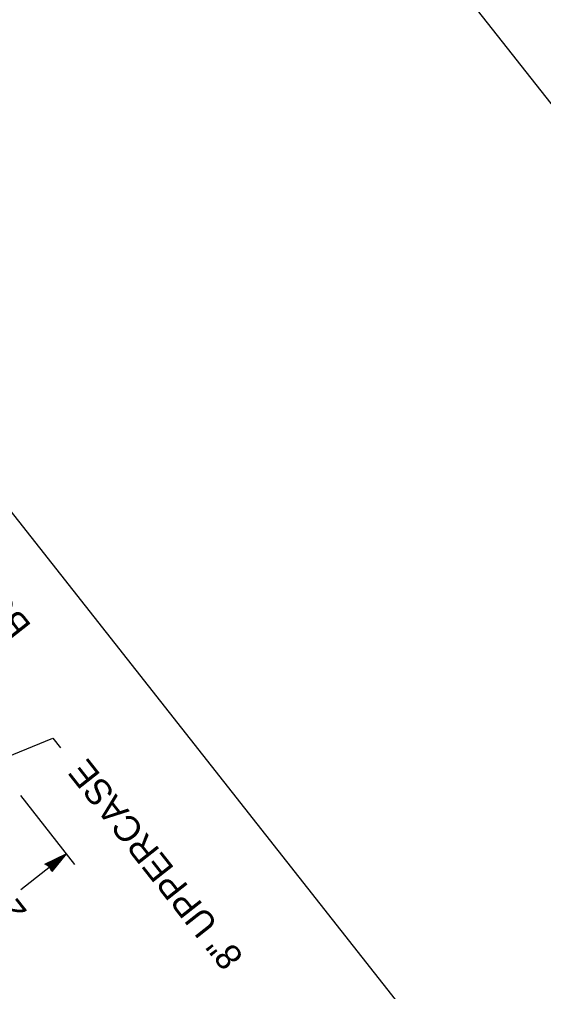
# Model space of a CAD drawing. Extents: x 671946 to 673995, y 1673066 to 1674936.
# Drawn here: x 672764.3 to 672849.6, y 1673606 to 1673764.1 of the extents above; entities that cross this region are included whole.
import ezdxf

# ---------------------------------------------------------------- set-up
doc = ezdxf.new("R2010")
doc.units = 0
doc.layers.add('1', color=7, linetype='Continuous')
doc.layers.add('Level 1', color=7, linetype='Continuous')

msp = doc.modelspace()

# ---------------------------------------------------------------- linework, layer by layer
at = {"layer": '1'}
msp.add_line((672460.47, 1674245.5), (673047.73, 1673500.58), dxfattribs=at)
at = {"layer": 'Level 1'}
for p, q in [((672685.68, 1673782.02), (672825.47, 1673604.71)), ((672764.49, 1673637.89), (672773.31, 1673626.69)), ((672764.56, 1673622.6), (672771.95, 1673628.43)), ((672768.48, 1673626.72), (672771.95, 1673628.43)), ((672768.68, 1673626.77), (672771.53, 1673628.07)), ((672768.84, 1673626.74), (672771.69, 1673628.16)), ((672768.96, 1673626.66), (672771.16, 1673627.81)), ((672768.96, 1673626.66), (672771.09, 1673627.69)), ((672769.14, 1673626.61), (672770.65, 1673627.35)), ((672769.31, 1673626.57), (672770.27, 1673627.08)), ((672771.16, 1673627.81), (672769.6, 1673626.1)), ((672771.95, 1673628.43), (672769.63, 1673625.52)), ((672771.73, 1673628.19), (672769.64, 1673625.67)), ((672771.09, 1673627.69), (672769.64, 1673625.97)), ((672771.38, 1673627.91), (672769.65, 1673625.83)), ((672770.65, 1673627.35), (672769.66, 1673626.24)), ((672770.27, 1673627.08), (672769.69, 1673626.37)), ((672770.11, 1673626.99), (672770.36, 1673627.09)), ((672770.72, 1673627.44), (672770.29, 1673627.23)), ((672770.36, 1673627.09), (672770.72, 1673627.44)), ((672771.48, 1673628.13), (672770.68, 1673627.7)), ((672770.68, 1673627.7), (672771.38, 1673627.91)), ((672771.69, 1673628.16), (672771.48, 1673628.13)), ((672771.53, 1673628.07), (672771.73, 1673628.19)), ((672769.3, 1673626.23), (672768.63, 1673626.7)), ((672768.63, 1673626.7), (672768.85, 1673626.64)), ((672768.99, 1673626.59), (672768.68, 1673626.77)), ((672768.85, 1673626.64), (672768.84, 1673626.74)), ((672769.51, 1673626.09), (672768.96, 1673626.66)), ((672769.64, 1673625.97), (672768.96, 1673626.66)), ((672769.23, 1673626.28), (672768.99, 1673626.59)), ((672769.6, 1673626.1), (672769.14, 1673626.61)), ((672769.58, 1673626.51), (672769.22, 1673626.5)), ((672769.22, 1673626.5), (672769.6, 1673626.23)), ((672769.63, 1673625.52), (672769.23, 1673626.28)), ((672769.64, 1673625.67), (672769.3, 1673626.23)), ((672769.66, 1673626.24), (672769.31, 1673626.57)), ((672769.41, 1673626.52), (672769.93, 1673626.79)), ((672769.69, 1673626.37), (672769.41, 1673626.52)), ((672769.65, 1673625.83), (672769.51, 1673626.09)), ((672769.66, 1673626.45), (672769.58, 1673626.51)), ((672769.6, 1673626.23), (672770.11, 1673626.99)), ((672769.93, 1673626.79), (672769.66, 1673626.45))]:
    msp.add_line(p, q, dxfattribs=at)
msp.add_lwpolyline([(672747.09, 1673637.95), (672769.8, 1673647.2), (672771.02, 1673645.65)], dxfattribs=at)

# ---------------------------------------------------------------- texts
for s, p in [('BORDER STRIP', (672766.42, 1673665.49)), ('8" UPPERCASE', (672800.94, 1673611.71)), ('26"', (672765.74, 1673619.02))]:
    msp.add_text(s, height=4.2, rotation=128.2505, dxfattribs=at).set_placement(p)

doc.saveas('drawing.dxf')
